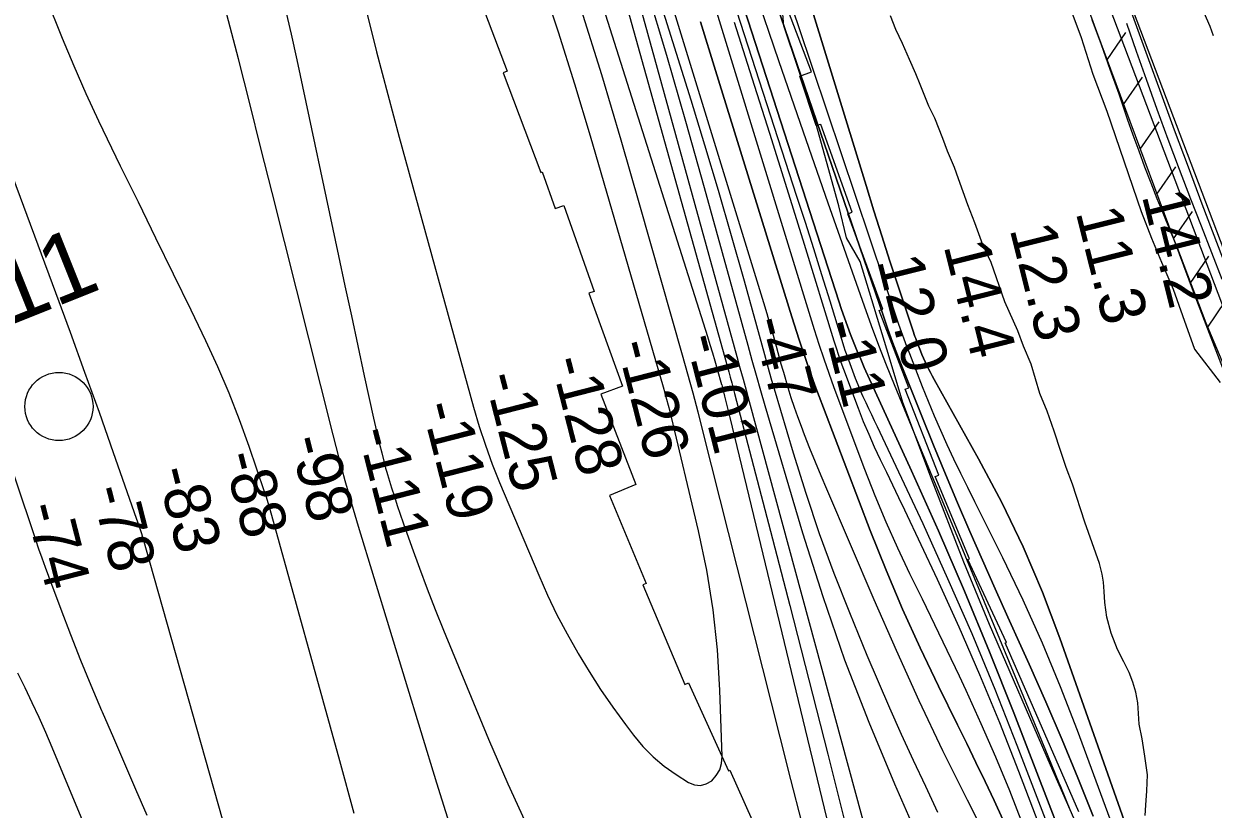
# Model space of a CAD drawing. Extents: x 3625074 to 3663148, y 511451 to 537151.
# Drawn here: x 3632002 to 3633748, y 527777 to 528929 of the extents above; entities that cross this region are included whole.
import ezdxf

# ---------------------------------------------------------------- set-up
doc = ezdxf.new("R2010")
doc.units = 0
for name, color, linetype in [('V-FLOD-BASE', 7, 'Continuous'), ('V-LEVE-TOET', 7, 'Continuous'), ('V-RIVR-EDGE', 7, 'Continuous'), ('V-RIVR-IDEN', 7, 'Continuous'), ('V-RIVR-MILE', 7, 'Continuous'), ('V-RIVR-RANG', 7, 'Continuous'), ('V-ROAD-CNTR', 7, 'Continuous'), ('V-RRAP-FSHR', 7, 'Continuous'), ('V-RRAP-RVMT', 7, 'Continuous'), ('V-SITE-VEGE', 7, 'Continuous'), ('V-SURV-LINE', 7, 'Continuous'), ('V-TOPO-DPTH', 7, 'Continuous'), ('V-TOPO-MAJR', 7, 'Continuous'), ('V-TOPO-MINR', 7, 'Continuous'), ('V-TOPO-WATR', 7, 'Continuous')]:
    doc.layers.add(name, color=color, linetype=linetype)

msp = doc.modelspace()

# ---------------------------------------------------------------- linework, layer by layer
at = {"layer": 'V-FLOD-BASE'}
msp.add_lwpolyline([(3633760.8, 528553.3), (3633745.7, 528592.7), (3633730.4, 528632), (3633714.9, 528671.2), (3633698.3, 528714.9), (3633681.9, 528758.8), (3633665.7, 528802.7), (3633649.7, 528846.7), (3633635.4, 528887.9), (3633620.8, 528929.1)], dxfattribs=at)
at = {"layer": 'V-LEVE-TOET'}
msp.add_line((3633684.2, 528626), (3633694, 528603), dxfattribs=at)
for points in [[(3633569.9, 528934.7), (3633583.2, 528898.4), (3633596.2, 528862.2), (3633609.1, 528825.8), (3633621.6, 528789.3), (3633629.9, 528765.7), (3633638.4, 528742.2), (3633647.1, 528718.8), (3633656.1, 528695.5), (3633665.2, 528672.2), (3633674.6, 528649), (3633684.2, 528626)], [(3633733.8, 528945.1), (3633742.7, 528924.9), (3633747.9, 528911.5)], [(3633694, 528603), (3633704.5, 528574.6), (3633715.2, 528546.3), (3633726.1, 528518.1), (3633737.2, 528490), (3633748.6, 528462), (3633760.2, 528434), (3633766, 528416.7), (3633772.1, 528399.4), (3633778.3, 528382.2), (3633784.8, 528365), (3633791.4, 528347.9), (3633798.2, 528330.9), (3633805.2, 528314)]]:
    msp.add_lwpolyline(points, dxfattribs=at)
at = {"layer": 'V-RIVR-EDGE'}
msp.add_lwpolyline([(3633556, 527734.7), (3633509.1, 527840.9), (3633419.5, 528047.6), (3633381.8, 528139), (3633334.3, 528261), (3633292.3, 528373.2), (3633272.2, 528440.1), (3633229.7, 528579.9), (3633209.5, 528614.9), (3633198.6, 528661.4), (3633159.8, 528800.6), (3633117.8, 528925.7), (3633114.8, 528960.7)], dxfattribs=at)
at = {"layer": 'V-RIVR-MILE'}
msp.add_circle((3632054, 528367.2), 50, dxfattribs=at)
at = {"layer": 'V-ROAD-CNTR'}
msp.add_lwpolyline([(3633555.4, 529139.1), (3633579.6, 529074.8), (3633603.6, 529010.4), (3633627.4, 528946), (3633650.9, 528881.4), (3633670.7, 528827.1), (3633690.7, 528772.9), (3633710.9, 528718.8), (3633731.3, 528664.7), (3633798, 528489.3)], dxfattribs=at)
at = {"layer": 'V-RRAP-FSHR'}
for p, q in [((3633592, 528875.7), (3633619.7, 528915.9)), ((3633616.3, 528810.1), (3633644.1, 528850.3)), ((3633640.7, 528744.5), (3633668.5, 528784.7)), ((3633665.1, 528678.9), (3633692.8, 528719)), ((3633689.5, 528613.2), (3633717.2, 528653.4)), ((3633713.9, 528547.6), (3633741.6, 528587.8)), ((3633738.9, 528482.2), (3633766.2, 528522.8))]:
    msp.add_line(p, q, dxfattribs=at)
msp.add_lwpolyline([(3631673.9, 532278.1), (3631870.7, 531995.4), (3632026.6, 531760.3), (3632223.6, 531470.9), (3632511.5, 531032.6), (3632750.5, 530684.2), (3632899.2, 530467.4), (3632993.3, 530316.6), (3633085.4, 530131), (3633184.5, 529917.7), (3633256.5, 529764.5), (3633343, 529548.3), (3633478.2, 529185.2), (3633576.4, 528917.5), (3633718.3, 528535.8), (3633831.8, 528240.8)], dxfattribs=at)
at = {"layer": 'V-RRAP-RVMT'}
for p, q in [((3632661.5, 528991.1), (3632711.6, 528859)), ((3633158.3, 528858.3), (3633108.1, 528990.5)), ((3632711.6, 528859), (3632706, 528856.8)), ((3632706, 528856.8), (3632761.3, 528710.6)), ((3633141.1, 528851.9), (3633158.3, 528858.3)), ((3633165.4, 528779.3), (3633141.1, 528851.9)), ((3633171.8, 528781), (3633165.4, 528779.3)), ((3633218, 528652.4), (3633171.8, 528781)), ((3632761.3, 528710.6), (3632763.3, 528711.4)), ((3632763.3, 528711.4), (3632782, 528657.7)), ((3632782, 528657.7), (3632794.8, 528662.2)), ((3632794.8, 528662.2), (3632839.2, 528536.1)), ((3633211.4, 528650), (3633218, 528652.4)), ((3633262.8, 528510.2), (3633211.4, 528650)), ((3632839.2, 528536.1), (3632831.4, 528533.3)), ((3632831.4, 528533.3), (3632880.8, 528397.2)), ((3633257.5, 528508.3), (3633262.8, 528510.2)), ((3633300.9, 528394.6), (3633257.5, 528508.3)), ((3632880.8, 528397.2), (3632849.1, 528385.2)), ((3633295.6, 528392.7), (3633300.9, 528394.6)), ((3632849.1, 528385.2), (3632900.7, 528252.9)), ((3633345.1, 528266.6), (3633295.6, 528392.7)), ((3633339.8, 528264.5), (3633345.1, 528266.6)), ((3633390.1, 528143.9), (3633339.8, 528264.5)), ((3632900.7, 528252.9), (3632861.9, 528236.9)), ((3632861.9, 528236.9), (3632915.5, 528107.6)), ((3633387.7, 528143), (3633390.1, 528143.9)), ((3633444.3, 528021.3), (3633387.7, 528143)), ((3632915.5, 528107.6), (3632910.6, 528105.6)), ((3632910.6, 528105.6), (3632972.6, 527959.7)), ((3633442.5, 528020.5), (3633444.3, 528021.3)), ((3633550.4, 527772.5), (3633442.5, 528020.5)), ((3632972.6, 527959.7), (3632978, 527961.9)), ((3632978, 527961.9), (3633036.3, 527833)), ((3633036.3, 527833), (3633038.5, 527833.9)), ((3633038.5, 527833.9), (3633089.3, 527720.3))]:
    msp.add_line(p, q, dxfattribs=at)
at = {"layer": 'V-SITE-VEGE'}
for points in [[(3633531.6, 528969.3), (3633554.1, 528908.6), (3633571.1, 528854.6), (3633591.8, 528800.5), (3633641.9, 528653.2), (3633657.4, 528614.1), (3633671.8, 528579), (3633689, 528539.3), (3633702.7, 528500.8), (3633720.5, 528451.4), (3633758.2, 528402.6)], [(3633647.9, 527767.3), (3633649, 527782.3), (3633650.2, 527803.5), (3633651.4, 527827.2), (3633647.5, 527854.3), (3633643.6, 527879.8), (3633639.1, 527901.3), (3633637.4, 527932.5), (3633634.3, 527948.2), (3633630, 527963.1), (3633624.4, 527977.3), (3633616.6, 527992.6), (3633607.1, 528010.7), (3633598.1, 528035), (3633591.5, 528058), (3633588.6, 528079.6), (3633587.9, 528096), (3633586.9, 528109.6), (3633584.6, 528121.5), (3633580.7, 528136.8), (3633559.5, 528197.6), (3633541.5, 528253.4), (3633532, 528277.9), (3633524, 528301.3), (3633514.3, 528330.9), (3633504.3, 528360.3), (3633493.4, 528386.3), (3633480.7, 528429.3), (3633469.3, 528455.9), (3633461.3, 528478.4), (3633442.2, 528520.8), (3633422, 528578.3), (3633409.9, 528604.2), (3633398, 528636.8), (3633387.9, 528663.1), (3633373.9, 528701.4), (3633368.1, 528717.7), (3633357.8, 528741.6), (3633351, 528760.2), (3633339.1, 528790.4), (3633330.3, 528807.6), (3633317.9, 528839.4), (3633311.4, 528855), (3633302, 528876.4), (3633291.9, 528899.5), (3633282.2, 528920.2), (3633274.4, 528940.1)]]:
    msp.add_lwpolyline(points, dxfattribs=at)
at = {"layer": 'V-SURV-LINE'}
for points in [[(3633845.2, 528296), (3633265.1, 529825)], [(3633293.1, 529835.7), (3633873.2, 528306.7)]]:
    msp.add_lwpolyline(points, dxfattribs=at)
at = {"layer": 'V-TOPO-DPTH'}
for points in [[(3633052.9, 529295.1), (3633238.3, 528691.6), (3633249.9, 528654.5), (3633261.6, 528617.5), (3633273.5, 528580.5), (3633285.6, 528543.6), (3633308, 528476.1), (3633309, 528473), (3633310.1, 528469.9), (3633311.2, 528466.9), (3633312.4, 528463.8), (3633318.2, 528449), (3633320.4, 528443.6), (3633322.7, 528438.2), (3633325.1, 528432.9), (3633327.5, 528427.6), (3633330.1, 528422.4), (3633332.8, 528417.2), (3633335.5, 528412.1), (3633338.3, 528407), (3633403.6, 528290.6), (3633437.4, 528226.6), (3633469, 528161.6), (3633497.1, 528095), (3633522.9, 528027.3), (3633669.8, 527610.4)], [(3632958.6, 529262.8), (3633198.4, 528521.9), (3633202.5, 528509.5), (3633206.8, 528497.2), (3633211.2, 528484.9), (3633215.7, 528472.7), (3633220.4, 528460.6), (3633225.3, 528448.5), (3633230.5, 528436.5), (3633235.8, 528424.6), (3633305.2, 528272.9), (3633344.5, 528184.9), (3633382.8, 528096.4), (3633419.5, 528007.3), (3633455.1, 527917.7), (3633572.3, 527614.8)], [(3633572.3, 527614.8), (3633455.1, 527917.7), (3633419.5, 528007.3), (3633382.8, 528096.4), (3633344.5, 528184.9), (3633305.2, 528272.9), (3633235.8, 528424.6), (3633230.5, 528436.5), (3633225.3, 528448.5), (3633220.4, 528460.6), (3633215.7, 528472.7), (3633211.2, 528484.9), (3633206.8, 528497.2), (3633202.5, 528509.5), (3633198.4, 528521.9), (3632958.6, 529262.8)], [(3633055.4, 529107.6), (3633263.8, 528499.9), (3633270.5, 528480.8), (3633277.4, 528461.7), (3633284.6, 528442.7), (3633292, 528423.8), (3633320.1, 528353.1), (3633337.2, 528310.5), (3633354.7, 528268.2), (3633372.6, 528225.9), (3633390.8, 528183.9), (3633409.3, 528141.9), (3633427.9, 528100), (3633446.6, 528058.1), (3633465.4, 528016.3), (3633477.6, 527989.5), (3633502.1, 527934.1), (3633526, 527878.5), (3633549, 527822.5), (3633571.5, 527766.2)], [(3633571.5, 527766.2), (3633549, 527822.5), (3633526, 527878.5), (3633502.1, 527934.1), (3633477.6, 527989.5), (3633465.4, 528016.3), (3633446.6, 528058.1), (3633427.9, 528100), (3633409.3, 528141.9), (3633390.8, 528183.9), (3633372.6, 528225.9), (3633354.7, 528268.2), (3633337.2, 528310.5), (3633320.1, 528353.1), (3633292, 528423.8), (3633284.6, 528442.7), (3633277.4, 528461.7), (3633270.5, 528480.8), (3633263.8, 528499.9), (3633055.4, 529107.6)], [(3633001.7, 529002.5), (3633162.3, 528480), (3633169.1, 528458.6), (3633176.2, 528437.3), (3633183.6, 528416.1), (3633191.3, 528395), (3633236.2, 528275.3), (3633251.4, 528236.5), (3633267.4, 528198), (3633284.5, 528160.1), (3633302.3, 528122.4), (3633320.7, 528084.9), (3633338.9, 528047.4), (3633356.9, 528009.8), (3633374.8, 527972.2), (3633384.8, 527951), (3633407, 527902.4), (3633428.4, 527853.5), (3633448.7, 527804.1), (3633468.1, 527754.4)], [(3633001.7, 529002.5), (3633162.3, 528480), (3633169.1, 528458.6), (3633176.2, 528437.3), (3633183.6, 528416.1), (3633191.3, 528395), (3633236.2, 528275.3), (3633251.4, 528236.5), (3633267.4, 528198), (3633284.5, 528160.1), (3633302.3, 528122.4), (3633320.7, 528084.9), (3633338.9, 528047.4), (3633356.9, 528009.8), (3633374.8, 527972.2), (3633384.8, 527951), (3633407, 527902.4), (3633428.4, 527853.5), (3633448.7, 527804.1), (3633468.1, 527754.4)], [(3633439.1, 527761.6), (3633426.3, 527789.5), (3633413, 527817.3), (3633399.6, 527845.1), (3633386.1, 527872.8), (3633372.5, 527900.4), (3633344.6, 527956.9), (3633317.7, 528013.2), (3633291.9, 528069.9), (3633267.7, 528127.3), (3633244.6, 528185.2), (3633175.7, 528365.3), (3633163.4, 528398.5), (3633151.5, 528431.7), (3633140.3, 528465.2), (3633129.5, 528498.9), (3633017.5, 528860.2), (3632995.4, 528931.4)], [(3632995.4, 528931.4), (3633017.5, 528860.2), (3633129.5, 528498.9), (3633140.3, 528465.2), (3633151.5, 528431.7), (3633163.4, 528398.5), (3633175.7, 528365.3), (3633244.6, 528185.2), (3633267.7, 528127.3), (3633291.9, 528069.9), (3633317.7, 528013.2), (3633344.6, 527956.9), (3633372.5, 527900.4), (3633386.1, 527872.8), (3633399.6, 527845.1), (3633413, 527817.3), (3633426.3, 527789.5), (3633439.1, 527761.6)], [(3633534.4, 527643.6), (3633462.7, 527831.7), (3633434.6, 527903), (3633405.5, 527973.7), (3633374.8, 528043.8), (3633343, 528113.5), (3633295.3, 528215), (3633286.5, 528233.5), (3633277.7, 528252), (3633268.8, 528270.5), (3633259.8, 528288.9), (3633251, 528307.4), (3633242.7, 528326.1), (3633234.8, 528345), (3633227.4, 528364.1), (3633205.8, 528421.7), (3633202, 528431.9), (3633198.4, 528442.2), (3633195, 528452.6), (3633191.7, 528463), (3633147.9, 528605.1), (3633122.6, 528686.5), (3633097.1, 528767.9), (3633071.3, 528849.1), (3633045.2, 528930.3)], [(3633534.4, 527643.6), (3633462.7, 527831.7), (3633434.6, 527903), (3633405.5, 527973.7), (3633374.8, 528043.8), (3633343, 528113.5), (3633295.3, 528215), (3633286.5, 528233.5), (3633277.7, 528252), (3633268.8, 528270.5), (3633259.8, 528288.9), (3633251, 528307.4), (3633242.7, 528326.1), (3633234.8, 528345), (3633227.4, 528364.1), (3633205.8, 528421.7), (3633202, 528431.9), (3633198.4, 528442.2), (3633195, 528452.6), (3633191.7, 528463), (3633147.9, 528605.1), (3633122.6, 528686.5), (3633097.1, 528767.9), (3633071.3, 528849.1), (3633045.2, 528930.3)]]:
    msp.add_lwpolyline(points, dxfattribs=at)
at = {"layer": 'V-TOPO-MAJR'}
for points in [[(3632629.5, 527747.7), (3632608.7, 527814.5), (3632493.6, 528191.1), (3632483.7, 528224.6), (3632474.1, 528258.1), (3632465, 528291.7), (3632456.2, 528325.5), (3632367, 528681.1), (3632350.5, 528746.4), (3632334, 528811.7), (3632317.3, 528877), (3632300.6, 528942.2), (3632274.7, 529042.7), (3632270.7, 529057.6), (3632266.6, 529072.6), (3632262.3, 529087.4), (3632257.9, 529102.3), (3632152, 529447.7), (3632126.9, 529526.7), (3632100.9, 529605.3), (3632073.4, 529683.5), (3632044.9, 529761.3), (3631993.6, 529897.6)], [(3633452.1, 527660.4), (3633387, 527789.6), (3633351.2, 527862.4), (3633316.3, 527935.5), (3633282.8, 528009.3), (3633250.2, 528083.5), (3633180.6, 528245.8), (3633172.3, 528265.7), (3633164, 528285.6), (3633156, 528305.6), (3633148.2, 528325.6), (3633143.5, 528337.9), (3633138.2, 528351.9), (3633133.3, 528366), (3633128.6, 528380.2), (3633124.2, 528394.5), (3633117.5, 528417.2), (3633116.6, 528420.2), (3633115.8, 528423.2), (3633114.9, 528426.2), (3633114, 528429.3), (3633106.9, 528455.2), (3633102.4, 528471.2), (3633097.8, 528487.2), (3633093.1, 528503.2), (3633088.3, 528519.1), (3632871.4, 529225.6)], [(3632776.2, 529193.6), (3633005.6, 528469.9), (3633009.3, 528458), (3633012.9, 528446.1), (3633016.5, 528434.1), (3633019.9, 528422.1), (3633026.4, 528399.4), (3633026.6, 528398.8), (3633027.1, 528396.9), (3633030.8, 528382.5), (3633032.8, 528374.6), (3633034.8, 528366.7), (3633036.7, 528358.9), (3633038.7, 528351), (3633228.8, 527563.2)]]:
    msp.add_lwpolyline(points, dxfattribs=at)
at = {"layer": 'V-TOPO-MINR'}
for points in [[(3633669.8, 527610.4), (3633522.9, 528027.3), (3633497.1, 528095), (3633469, 528161.6), (3633437.4, 528226.6), (3633403.6, 528290.6), (3633338.3, 528407), (3633335.5, 528412.1), (3633332.8, 528417.2), (3633330.1, 528422.4), (3633327.5, 528427.6), (3633325.1, 528432.9), (3633322.7, 528438.2), (3633320.4, 528443.6), (3633318.2, 528449), (3633312.4, 528463.8), (3633311.2, 528466.9), (3633310.1, 528469.9), (3633309, 528473), (3633308, 528476.1), (3633285.6, 528543.6), (3633273.5, 528580.5), (3633261.6, 528617.5), (3633249.9, 528654.5), (3633238.3, 528691.6), (3633052.9, 529295.1)], [(3633558.7, 527613.2), (3633460.3, 527870.1), (3633427.8, 527952.2), (3633394.1, 528033.9), (3633358.6, 528114.7), (3633322, 528195.1), (3633255.1, 528337.6), (3633251, 528346.4), (3633246.8, 528355.1), (3633242.6, 528363.8), (3633238.4, 528372.6), (3633234.3, 528381.3), (3633230.3, 528390.2), (3633226.6, 528399.1), (3633223.1, 528408.2), (3633213, 528435.1), (3633211.2, 528439.9), (3633209.5, 528444.7), (3633207.9, 528449.6), (3633206.4, 528454.5), (3633185.6, 528521.7), (3633173.6, 528560.2), (3633161.6, 528598.6), (3633149.4, 528637), (3633137, 528675.4), (3632944.7, 529269.6)], [(3633572.3, 527614.8), (3633455.1, 527917.7), (3633419.5, 528007.3), (3633382.8, 528096.4), (3633344.5, 528184.9), (3633305.2, 528272.9), (3633235.8, 528424.6), (3633230.5, 528436.5), (3633225.3, 528448.5), (3633220.4, 528460.6), (3633215.7, 528472.7), (3633211.2, 528484.9), (3633206.8, 528497.2), (3633202.5, 528509.5), (3633198.4, 528521.9), (3632958.6, 529262.8)], [(3633343.6, 527771.8), (3633325.9, 527810), (3633308.1, 527848.1), (3633290.4, 527886.3), (3633273.1, 527924.7), (3633256.4, 527963.3), (3633240.1, 528002.1), (3633214.4, 528064.5), (3633191.7, 528122.3), (3633170.1, 528180.5), (3633150.4, 528239.4), (3633131.8, 528298.6), (3633104, 528392.7), (3633100.3, 528405.3), (3633096.7, 528417.8), (3633093.1, 528430.4), (3633089.6, 528443.1), (3633059.8, 528551.2), (3633041.1, 528617.8), (3633021.9, 528684.2), (3633002, 528750.4), (3632981.6, 528816.5), (3632849.5, 529237)], [(3632845.7, 529103.3), (3633036.9, 528418.1), (3633039.1, 528410.2), (3633041.3, 528402.2), (3633043.4, 528394.3), (3633045.5, 528386.3), (3633098.3, 528184.4), (3633126.6, 528075.4), (3633154.6, 527966.3), (3633182.2, 527857.1), (3633209.5, 527747.9)], [(3632504.5, 528950.4), (3632520.2, 528887.5), (3632536.5, 528824.8), (3632553.4, 528762.2), (3632662.4, 528366.2), (3632670.7, 528338.1), (3632679.7, 528310.3), (3632689.9, 528282.9), (3632700.7, 528255.8), (3632758.2, 528119.8), (3632771.1, 528090.7), (3632784.8, 528061.9), (3632799.6, 528033.7), (3632815.2, 528005.9), (3632815.7, 528005.1), (3632832, 527978.3), (3632848.9, 527951.9), (3632866.8, 527926.1), (3632885.3, 527900.7), (3632897.2, 527885), (3632911, 527868.6), (3632925.8, 527853.4), (3632942.1, 527839.8), (3632959.5, 527827.4), (3632977.8, 527815.7), (3632986.6, 527812.4), (3632995.3, 527811.3), (3633003.7, 527813.7), (3633011.9, 527818.3), (3633018.6, 527826), (3633023.6, 527834.4), (3633026.3, 527843.8), (3633027.3, 527853.9), (3633024, 527951), (3633020.2, 528010.1), (3633014.1, 528068.8), (3633004.5, 528127.1), (3632992.5, 528185), (3632950.7, 528359.8), (3632948.5, 528368.8), (3632946.2, 528377.7), (3632943.8, 528386.6), (3632941.3, 528395.5), (3632833.9, 528763.8), (3632810.9, 528840.2), (3632787.1, 528916.4), (3632761.9, 528992.1)], [(3633251.3, 527696.9), (3633067.2, 528374.2), (3633062.7, 528390.6), (3633058.3, 528407), (3633053.8, 528423.4), (3633049.2, 528439.9), (3632897.6, 528989.3)], [(3633647.9, 527622.5), (3633548.8, 527891.8), (3633523.9, 527956.2), (3633497.5, 528020.1), (3633469, 528083), (3633439, 528145.2), (3633397.8, 528227.5), (3633387.5, 528248.2), (3633377.4, 528269), (3633367.4, 528289.9), (3633357.6, 528310.9), (3633348.1, 528332), (3633338.9, 528353.2), (3633330, 528374.6), (3633321.3, 528396.1), (3633302.4, 528444.3), (3633298.2, 528455.1), (3633294.2, 528465.9), (3633290.4, 528476.8), (3633286.6, 528487.7), (3633139, 528925.7), (3633116.4, 528992.9)], [(3633352.5, 527649.1), (3633280.5, 527813.1), (3633242.8, 527903.7), (3633207.3, 527995.2), (3633175.4, 528087.9), (3633145.8, 528181.5), (3633090.5, 528368.2), (3633084, 528390.3), (3633077.6, 528412.5), (3633071.4, 528434.6), (3633065.2, 528456.8), (3633001.4, 528688.1), (3632974.1, 528785.2), (3632946.1, 528882), (3632917, 528978.6)], [(3633539, 527773), (3633524, 527809.4), (3633521.7, 527814.9), (3633505.6, 527854.1), (3633489.4, 527893.3), (3633473.3, 527932.5), (3633457.1, 527971.7), (3633426.4, 528045.9), (3633398, 528114.3), (3633369.7, 528182.7), (3633341.4, 528251.1), (3633313, 528319.5), (3633280, 528399.2), (3633268.4, 528427.8), (3633257.2, 528456.6), (3633246.3, 528485.6), (3633235.9, 528514.6), (3633182.9, 528665.3), (3633146.4, 528769.8), (3633110.4, 528874.5), (3633074.8, 528979.4)], [(3632487.3, 527770.4), (3632466, 527847.3), (3632363.9, 528216), (3632362, 528222.6), (3632360.1, 528229.2), (3632358, 528235.7), (3632355.8, 528242.2), (3632333.1, 528308.5), (3632318.8, 528347.9), (3632303.6, 528386.9), (3632287, 528425.3), (3632269.5, 528463.4), (3632247.8, 528508.4), (3632222.2, 528561.3), (3632196.4, 528614.2), (3632170.5, 528667), (3632144.4, 528719.8), (3632131.4, 528746.2), (3632112.3, 528785.9), (3632093.8, 528825.9), (3632076.2, 528866.4), (3632059.3, 528907.1), (3632035.2, 528967)], [(3632743.2, 527748.3), (3632713.1, 527813.2), (3632684.6, 527878.9), (3632618.9, 528038.7), (3632606.8, 528068.9), (3632594.9, 528099.2), (3632583.5, 528129.7), (3632572.4, 528160.3), (3632559.7, 528196.1), (3632555.2, 528208.9), (3632550.9, 528221.7), (3632546.7, 528234.6), (3632542.6, 528247.5), (3632536.5, 528267.2), (3632535.6, 528270.3), (3632534.7, 528273.4), (3632533.8, 528276.5), (3632533, 528279.7), (3632528.2, 528298.9), (3632525, 528311.7), (3632522, 528324.5), (3632519, 528337.4), (3632516.2, 528350.2), (3632502.6, 528412.4), (3632493.1, 528456.4), (3632483.6, 528500.3), (3632474.2, 528544.3), (3632464.8, 528588.3), (3632403.5, 528875.9), (3632395.2, 528913.6), (3632386.5, 528951.2)], [(3632820.5, 528949.1), (3632850, 528854), (3632878.4, 528758.6), (3632906.1, 528663), (3632968.7, 528442.8), (3632976.4, 528415.1), (3632984, 528387.3), (3632991.4, 528359.4), (3632998.5, 528331.5), (3633112, 527882), (3633127.7, 527819.9), (3633143.4, 527757.7)], [(3633439.1, 527761.6), (3633426.3, 527789.5), (3633413, 527817.3), (3633399.6, 527845.1), (3633386.1, 527872.8), (3633372.5, 527900.4), (3633344.6, 527956.9), (3633317.7, 528013.2), (3633291.9, 528069.9), (3633267.7, 528127.3), (3633244.6, 528185.2), (3633175.7, 528365.3), (3633163.4, 528398.5), (3633151.5, 528431.7), (3633140.3, 528465.2), (3633129.5, 528498.9), (3633017.5, 528860.2), (3632995.4, 528931.4)], [(3633534.4, 527643.6), (3633462.7, 527831.7), (3633434.6, 527903), (3633405.5, 527973.7), (3633374.8, 528043.8), (3633343, 528113.5), (3633295.3, 528215), (3633286.5, 528233.5), (3633277.7, 528252), (3633268.8, 528270.5), (3633259.8, 528288.9), (3633251, 528307.4), (3633242.7, 528326.1), (3633234.8, 528345), (3633227.4, 528364.1), (3633205.8, 528421.7), (3633202, 528431.9), (3633198.4, 528442.2), (3633195, 528452.6), (3633191.7, 528463), (3633147.9, 528605.1), (3633122.6, 528686.5), (3633097.1, 528767.9), (3633071.3, 528849.1), (3633045.2, 528930.3)], [(3631917.5, 528888.2), (3632048.8, 528534.6), (3632070.4, 528476.1), (3632091.7, 528417.5), (3632112.8, 528358.8), (3632133.6, 528300), (3632167.5, 528203.6), (3632171.1, 528192.9), (3632174.6, 528182.2), (3632177.9, 528171.4), (3632181.1, 528160.5), (3632388.1, 527428.7)], [(3631868.8, 528620.1), (3632019.4, 528172.2), (3632024, 528158.7), (3632028.7, 528145.2), (3632033.6, 528131.8), (3632038.5, 528118.5), (3632056.6, 528070.1), (3632070.9, 528032.6), (3632085.7, 527995.3), (3632100.9, 527958.3), (3632116.6, 527921.4), (3632117.5, 527919.3), (3632133.9, 527881.4), (3632150.2, 527843.6), (3632166.5, 527805.7), (3632182.8, 527767.8)], [(3631993.4, 527976.5), (3632003.9, 527954.9), (3632014.3, 527933.2), (3632024.5, 527911.4), (3632034.2, 527889.5), (3632043.7, 527867.4), (3632100.9, 527730.2)]]:
    msp.add_lwpolyline(points, dxfattribs=at)
at = {"layer": 'V-TOPO-WATR'}
msp.add_lwpolyline([(3633571.5, 527766.2), (3633549, 527822.5), (3633526, 527878.5), (3633502.1, 527934.1), (3633477.6, 527989.5), (3633465.4, 528016.3), (3633446.6, 528058.1), (3633427.9, 528100), (3633409.3, 528141.9), (3633390.8, 528183.9), (3633372.6, 528225.9), (3633354.7, 528268.2), (3633337.2, 528310.5), (3633320.1, 528353.1), (3633292, 528423.8), (3633284.6, 528442.7), (3633277.4, 528461.7), (3633270.5, 528480.8), (3633263.8, 528499.9), (3633055.4, 529107.6)], dxfattribs=at)

# ---------------------------------------------------------------- texts
at = {"layer": 'V-RIVR-IDEN'}
msp.add_text('111', height=100, rotation=21.8538, dxfattribs=at).set_placement((3631911.4, 528457.7))
at = {"layer": 'V-RIVR-RANG'}
for s, rotation, p in [('14.2', 284.0783, (3633642.7, 528676.7)), ('11.3', 284.0783, (3633545.8, 528652.2)), ('12.3', 284.0783, (3633448.8, 528627.6)), ('14.4', 284.0783, (3633351.9, 528603)), ('12.0', 284.0783, (3633254.2, 528581.3)), ('-47', 284.3611, (3633069.9, 528492.5)), ('-11', 284.3611, (3633174.4, 528487.7)), ('-101', 284.3611, (3632973, 528467.7)), ('-126', 284.3611, (3632872.1, 528458.7)), ('-128', 284.3611, (3632775, 528434.7)), ('-125', 284.3611, (3632677.8, 528411.1)), ('-119', 284.3611, (3632585.6, 528368.4)), ('-111', 284.3611, (3632492, 528330.6)), ('-98', 284.3611, (3632391.9, 528318.5)), ('-88', 284.3611, (3632294.7, 528295)), ('-83', 284.3611, (3632197.1, 528273)), ('-78', 284.3611, (3632100.9, 528245.3)), ('-74', 284.3611, (3632004.2, 528220))]:
    msp.add_text(s, height=67, rotation=rotation, dxfattribs=at).set_placement(p)

doc.saveas('drawing.dxf')
